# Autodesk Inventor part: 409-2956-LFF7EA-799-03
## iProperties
Created: 2010-11
Part Number: 409-2956-LFF7EA-799-03
Material: 3/4" OD TUBE - SS
Document SubType Name: Modeling
Designer: S. Boerckel
Engineer: Steve Boerckel
Mass: 309.983 g
Surface Area: 466.545 cm^2
Volume: 38.3643 cm^3
Density: 8.08 g/cm^3
Description: DRAIN TUBING
User Status: CUT/TUBE BEND
Length: 11.124 in
Author: S. Boerckel
Revision Number: 0
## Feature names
1. Sweep1
